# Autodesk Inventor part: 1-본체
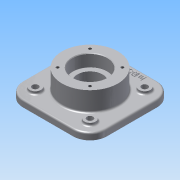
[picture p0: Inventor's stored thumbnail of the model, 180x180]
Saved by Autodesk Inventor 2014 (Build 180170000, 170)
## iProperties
Created: 2015-09
Part Number: 1-본체
Material: 알루미늄 6061
Document SubType Name: Modeling
Designer: study
Density: 2.71 g/cm^3
Appearance: 알루미늄 - 평지
Author: study
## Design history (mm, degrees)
sketch "스케치1"
  geometry: L1 (75, -75)-(-75, -75); L2 (-75, -75)-(-75, 75); L3 (-75, 75)-(75, 75); L4 (75, 75)-(75, -75); L5 (75, -75)-(-75, 75); L6 (-75, -75)-(75, 75); 1 further point
  constraints: 12 end point, 2 midpoint, 2 parallel, 1 horizontal, 1 perpendicular
  dimensions: "d0" = 150 distance of L2.end L3.end; "d1" = 150 distance of L3.end L1.start
extrude "돌출1" new body sketch "스케치1" stored distance "d2" = 12; taper "d3" = 0 deg
node "작업 평면1"
sketch "스케치2"
  geometry: C1 r 50 at (0, 0); 1 further point
  constraints: 1 centre point, 1 coincident
  dimensions: "d5" = 100 diameter of C1
extrude "돌출2" join sketch "스케치2" distance "d6" = 70; taper "d7" = 0 deg
hole "구멍1" diameter "d10" = 45; stored, may be unused: countersink angle "d14" = 90 deg, drill point angle "d16" = 118 deg; dims "d11" = 6, "d12" = 62, "d13" = 22, "d15" = 8, "d26" = 10, "d27" = 10
hole "구멍2" diameter "d19" = 62; stored, may be unused: countersink angle "d23" = 90 deg, drill point angle "d25" = 0 deg; dims "d20" = 6, "d21" = 4, "d22" = 2, "d24" = 22, "d62" = 10, "d63" = 10
fillet "모깎기1" dims "d28" = 30
sketch "스케치3"
  geometry: C1 r 50 at (0, 0) reference; C2 r 10 at (-49, 49); C3 r 10 at (49, 49); C4 r 10 at (49, -49); C5 r 10 at (-49, -49)
  constraints: 4 centre point, 3 equal radius, 2 horizontal alignment, 2 vertical alignment
  dimensions: "d29" = 20 diameter of C2; "d30" = 98 distance of C3.centre C2.centre; "d31" = 49 horizontal distance of C1.centre C2.centre; "d32" = 98 distance of C5.centre C2.centre; "d33" = 49 horizontal distance of C1.centre C5.centre
extrude "돌출3" join sketch "스케치3" distance "d34" = 5; taper "d35" = 0 deg
sketch "스케치4"
  geometry: C1 r 10 at (0, 0) reference; C2 r 10 at (0, -98) reference; C3 r 10 at (98, -98) reference; C4 r 10 at (98, 0) reference; 5 further points
  constraints: 4 coincident
hole "구멍3" sketch "스케치4" at (0, 0), (98, 0), (98, -98), (0, -98) diameter "d36" = 11; stored, may be unused: countersink angle "d40" = 90 deg, drill point angle "d42" = 118 deg; dims "d37" = 6, "d38" = 4, "d39" = 2, "d41" = 22
sketch "스케치5"
  geometry: L1 (28.991, -28.991)-(-28.991, -28.991); L2 (-28.991, -28.991)-(-28.991, 28.991); L3 (-28.991, 28.991)-(28.991, 28.991); L4 (28.991, 28.991)-(28.991, -28.991); L5 (28.991, -28.991)-(-28.991, 28.991); L6 (-28.991, -28.991)-(28.991, 28.991); C1 r 31 at (0, 0) reference; C2 r 50 at (0, 0) reference; 4 further points
  constraints: 12 end point, 4 coincident, 2 midpoint, 2 parallel, 2 perpendicular, 1 horizontal
  dimensions: "d46" = 41 distance of C1.centre L2.end
hole "구멍4" sketch "스케치5" at (-28.991, 28.991), (-28.991, -28.991), (28.991, -28.991), (28.991, 28.991) diameter "d47" = 4.917; stored, may be unused: countersink angle "d51" = 90 deg, drill point angle "d53" = 118 deg; dims "d48" = 10, "d49" = 4, "d50" = 2, "d52" = 13
node "작업 평면2"
sketch "스케치6"
  geometry: C1 r 50 at (0, 0) reference; 1 further point
  constraints: 1 vertical alignment, 1 other
  dimensions: "d54" = 65 distance of C1.centre point (0, 65)
feature "엠보싱1" sketch "스케치6" dims "d0" = 150, "d1" = 150, "d55" = 1, "d56" = 0
fillet "모깎기2" dims "d57" = 3, "d58" = 0.3
chamfer "모따기1" distance "d59" = 1; stored, may be unused: second distance "d60" = 2, angle "d61" = 45 deg
node "솔리드1"
mirror "대칭1"
node "투영된 루프1"
node "투영된 루프2"
node "투영된 루프3"
other parameters: "d4" = 23
